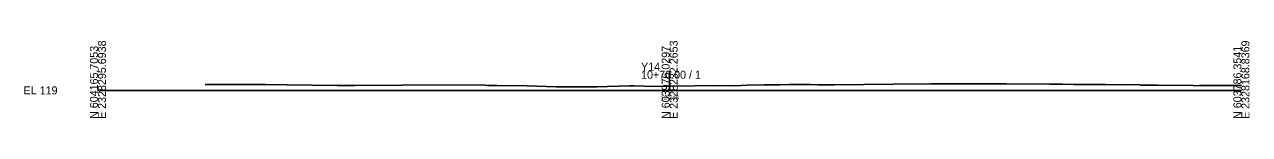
# Model space of a CAD drawing. Extents: x -26 to 2328312, y 990 to 603967.
# Drawn here: x 1374.3 to 1802.8, y 990.3 to 1017.3 of the extents above; entities that cross this region are included whole.
import ezdxf

# ---------------------------------------------------------------- set-up
doc = ezdxf.new("R2010")
doc.units = 0
for name, color, linetype in [('Default', 7, 'Continuous'), ('Exist CMT Pavement', 7, 'Continuous'), ('Exist Cross Section Cell', 7, 'Continuous'), ('Exist XS Center Line Elevation Label', 7, 'Continuous'), ('Exist XS Ground Line', 7, 'Continuous'), ('Exist XS Void Line', 7, 'Continuous'), ('Prop XS Earthwork Shape', 7, 'Continuous')]:
    doc.layers.add(name, color=color, linetype=linetype)

msp = doc.modelspace()

# ---------------------------------------------------------------- linework, layer by layer
at = {"layer": 'Exist CMT Pavement'}
for points in [[(1599.9, 1001.48), (1599.9, 1001.58), (1600, 1001.58), (1600, 1001.48)], [(1600, 1001.48), (1600, 1001.58), (1600.1, 1001.58), (1600.1, 1001.48)]]:
    msp.add_lwpolyline(points, dxfattribs=at)
at = {"layer": 'Exist Cross Section Cell'}
for p, q in [((1600, 1000), (1600, 1006.89)), ((1400, 1000), (1600, 1000)), ((1600, 1000), (1800, 1000))]:
    msp.add_line(p, q, dxfattribs=at)
at = {"layer": 'Exist XS Ground Line'}
msp.add_lwpolyline([(1437.5, 1002.02), (1438.52, 1002.03), (1458.61, 1002.05), (1466.25, 1001.98), (1483.65, 1001.75), (1489.85, 1001.7), (1506.21, 1001.81), (1534.21, 1001.9), (1536.26, 1001.71), (1539.53, 1001.7), (1550.1, 1001.64), (1560.27, 1001.29), (1574.51, 1001.3), (1585.86, 1001.63), (1587.62, 1001.62), (1594.68, 1001.4), (1598.17, 1001.45), (1600, 1001.48), (1608.82, 1001.63), (1617.42, 1001.7), (1622.67, 1001.61), (1627.12, 1001.83), (1633.2, 1001.94), (1638.59, 1001.97), (1641.82, 1002.03), (1647.56, 1002.06), (1649.23, 1002.08), (1651.8, 1001.96), (1657.62, 1002), (1678.17, 1002.15), (1691.32, 1002.24), (1701.19, 1002.3), (1702.03, 1002.29), (1717.73, 1002.27), (1732.83, 1002.16), (1736.84, 1002.16), (1737.41, 1002.18), (1741.34, 1002.12), (1750.12, 1002.08), (1752.51, 1002.06), (1757.56, 1001.99), (1763.95, 1002.01), (1764.87, 1001.88), (1770.62, 1001.82), (1783.08, 1001.67), (1786.71, 1001.65), (1800, 1001.69)], dxfattribs=at)
at = {"layer": 'Exist XS Void Line'}
msp.add_lwpolyline([(1785.48, 1001.79), (1790.15, 1001.75), (1791, 1001.75), (1792.92, 1001.78), (1800, 1001.69)], dxfattribs=at)
at = {"layer": 'Prop XS Earthwork Shape'}
for points in [[(1599.9, 1001.48), (1600, 1001.48), (1600, 1001.58), (1599.9, 1001.58)], [(1600, 1001.48), (1600.1, 1001.48), (1600.1, 1001.58), (1600, 1001.58)]]:
    msp.add_lwpolyline(points, close=True, dxfattribs=at)

# ---------------------------------------------------------------- texts
at = {"layer": 'Default'}
msp.add_text('-', height=1.5, dxfattribs=at).set_placement((1399.63, 999.25))
at = {"layer": 'Exist Cross Section Cell'}
for s, p in [('E 2328295.6938', (1402.8, 990)), ('E 2328232.2653', (1602.8, 990)), ('E 2328168.8369', (1802.8, 990)), ('N 604165.7053', (1400, 990)), ('N 603976.0297', (1600, 990)), ('N 603786.3541', (1800, 990))]:
    msp.add_text(s, height=2.8, rotation=90, dxfattribs=at).set_placement(p)
for s, p in [('Y14', (1590, 1006.89)), ('10+70.00 / 1', (1590, 1004.09)), ('EL 119', (1374, 998.6))]:
    msp.add_text(s, height=2.8, dxfattribs=at).set_placement(p)
at = {"layer": 'Exist XS Center Line Elevation Label'}
msp.add_text('120.48', height=1.5, dxfattribs=at).set_placement((1596.88, 996.73))

doc.saveas('drawing.dxf')
